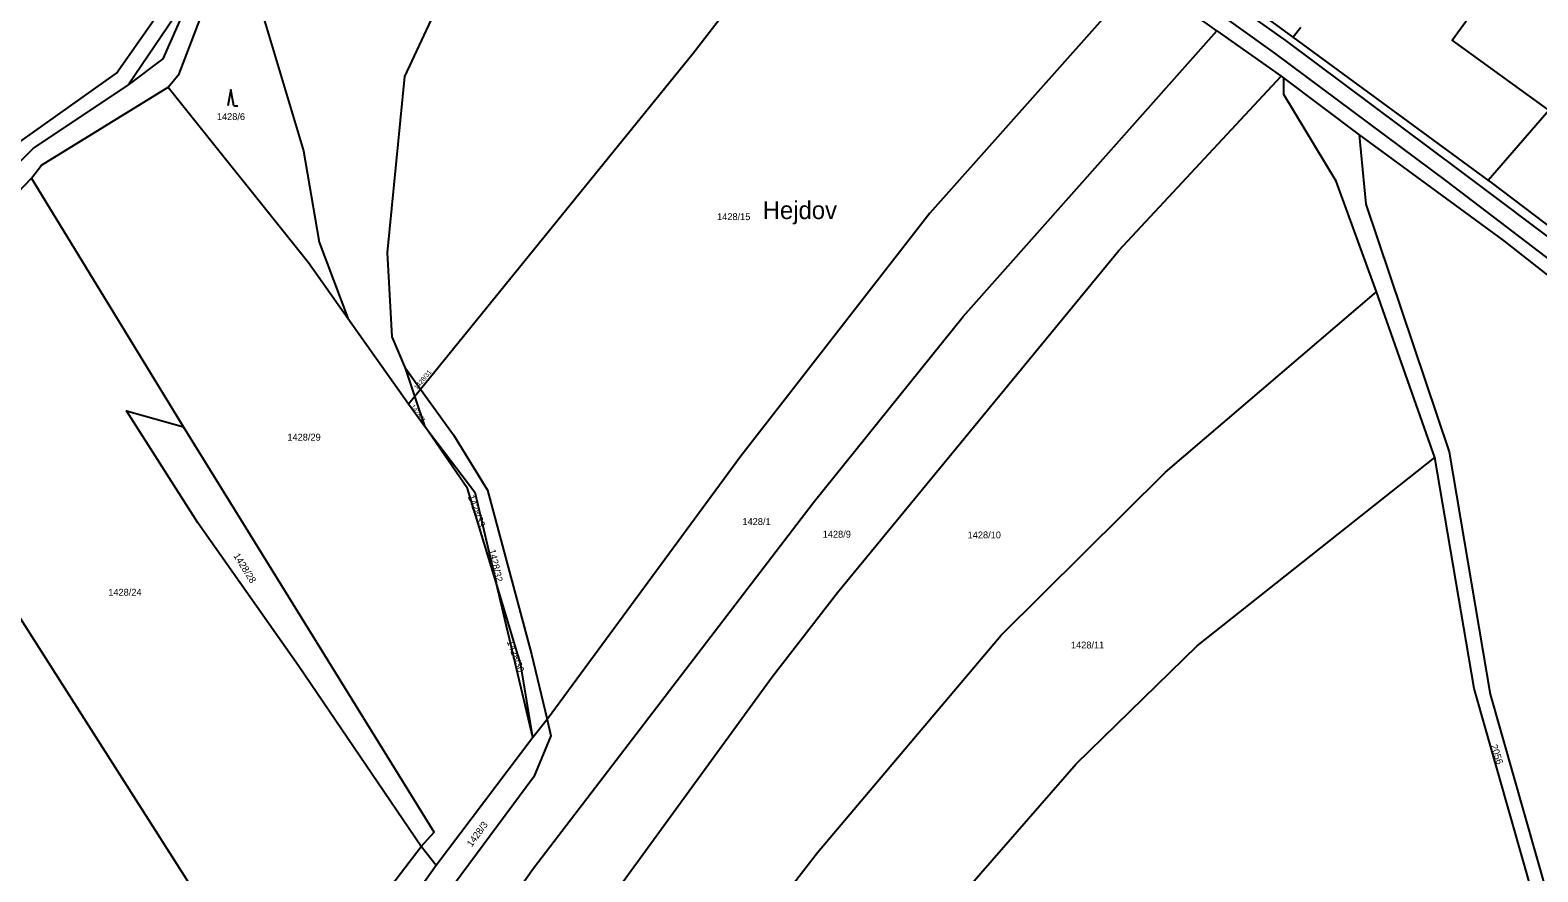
# Model space of a CAD drawing. Extents: x -679220 to -673243, y -1075091 to -1066557.
# Drawn here: x -677968.8 to -677596.9, y -1070610.2 to -1070402.6 of the extents above; entities that cross this region are included whole.
import ezdxf

# ---------------------------------------------------------------- set-up
doc = ezdxf.new("R2010")
doc.units = 0
for name, color, linetype in [('Hranice parcel', 7, 'Continuous'), ('Parcelní čísla', 7, 'Continuous'), ('Pop  PČ popisy', 7, 'Continuous'), ('Vnitřní kresba', 7, 'Continuous'), ('Značky kultur', 7, 'Continuous')]:
    doc.layers.add(name, color=color, linetype=linetype)

msp = doc.modelspace()

# ---------------------------------------------------------------- linework, layer by layer
at = {"layer": 'Hranice parcel'}
for p, q in [((-677676.01, -1070402.73), (-677694.91, -1070389.28)), ((-677676.01, -1070402.73), (-677660.17, -1070413.98)), ((-677655.29, -1070401.92), (-677657.23, -1070404.36)), ((-677609.13, -1070439.59), (-677657.23, -1070404.36)), ((-677660.17, -1070413.98), (-677659.51, -1070414.42)), ((-677659.51, -1070414.42), (-677640.92, -1070428.43)), ((-677930.97, -1070500.49), (-677968.48, -1070439.15)), ((-677622.29, -1070507.99), (-677636.62, -1070467.14)), ((-677890.42, -1070473.63), (-677875.44, -1070494.74)), ((-677873.92, -1070492.86), (-677876.21, -1070485.99)), ((-677876.21, -1070485.99), (-677872.51, -1070491.13)), ((-677875.44, -1070494.74), (-677873.92, -1070492.86)), ((-677873.92, -1070492.86), (-677872.51, -1070491.13)), ((-677871.38, -1070500.47), (-677873.92, -1070492.86)), ((-677875.44, -1070494.74), (-677871.38, -1070500.47)), ((-677844.81, -1070577.09), (-677853.87, -1070538.81)), ((-677841.24, -1070572.65), (-677844.81, -1070577.09)), ((-677844.81, -1070577.09), (-677868.63, -1070608.64)), ((-677906.8, -1070648.9), (-677872.33, -1070603.97)), ((-677868.63, -1070608.64), (-677872.33, -1070603.97)), ((-677868.63, -1070608.64), (-677896.62, -1070647.74))]:
    msp.add_line(p, q, dxfattribs=at)
for points in [[(-677594.18, -1070422.35), (-677617.99, -1070405.1), (-677595.86, -1070374.56), (-677562.79, -1070334.89), (-677527.98, -1070275.97), (-677483.78, -1070192.17), (-677443.31, -1070109.44)], [(-678202.72, -1070559.59), (-678196.24, -1070560.72), (-678173.74, -1070562.48), (-678126.52, -1070533.09), (-678089.52, -1070509.78), (-678070.97, -1070501.74), (-678009.17, -1070456.93), (-677947.5, -1070413.22), (-677923.47, -1070378.9), (-677909.43, -1070354.95), (-677894.19, -1070322.1), (-677883.78, -1070282.87), (-677858.64, -1070275.93)], [(-677855.84, -1070280.12), (-677880.02, -1070286.32), (-677890.13, -1070322.37), (-677903.96, -1070353.51), (-677931.48, -1070396.8), (-677944.62, -1070416.2)], [(-677944.62, -1070416.2), (-677936.01, -1070409.66), (-677930.66, -1070397.57), (-677918.45, -1070383.68), (-677909.53, -1070370.43), (-677886.19, -1070349.6), (-677870.36, -1070340.73), (-677870.09, -1070332.9), (-677876.85, -1070320.41), (-677873.44, -1070296.89), (-677853.32, -1070283.11)], [(-677876.21, -1070485.99), (-677879.53, -1070478.23), (-677880.65, -1070457.46), (-677876.4, -1070414), (-677860.23, -1070379.46), (-677858.39, -1070339.32), (-677865.38, -1070320.02), (-677859.97, -1070301.48), (-677838.54, -1070289.74)], [(-677872.51, -1070491.13), (-677805.2, -1070408.28), (-677756.66, -1070345.34)], [(-677657.23, -1070404.36), (-677700.73, -1070372.5), (-677730.02, -1070352.35)], [(-677934.76, -1070416.68), (-677932.07, -1070413.36), (-677926.94, -1070400.09), (-677915.46, -1070385.44)], [(-677915.46, -1070385.44), (-677901.39, -1070432.37), (-677897.5, -1070454.86), (-677890.42, -1070473.63)], [(-677694.91, -1070389.28), (-677746.88, -1070447.72), (-677793.45, -1070507.65), (-677841.24, -1070572.65)], [(-677874.94, -1070651.97), (-677873.69, -1070650.21), (-677844.6, -1070609.28), (-677775.61, -1070519.23), (-677738.63, -1070473.21), (-677676.01, -1070402.73)], [(-678001.62, -1070455.63), (-677993, -1070448.92), (-677976.44, -1070440.07), (-677967.96, -1070431.69), (-677944.62, -1070416.2)], [(-677854.13, -1070656.04), (-677853.11, -1070654.64), (-677785.75, -1070562.15), (-677769.67, -1070541.32), (-677700.26, -1070456.95), (-677660.17, -1070413.98)], [(-677636.62, -1070467.14), (-677646.59, -1070439.83), (-677659.5, -1070418.44), (-677659.51, -1070414.42)], [(-677968.48, -1070439.15), (-677966, -1070435.9), (-677934.76, -1070416.68)], [(-677934.76, -1070416.68), (-677900.16, -1070459.91), (-677890.42, -1070473.63)], [(-677609.13, -1070439.59), (-677605.88, -1070435.88), (-677594.18, -1070422.35)], [(-677640.92, -1070428.43), (-677605.25, -1070454.6), (-677571.87, -1070480.78), (-677536.71, -1070509.44), (-677502.3, -1070535.39), (-677460.61, -1070565.82), (-677445.99, -1070576.58)], [(-677640.92, -1070428.43), (-677639.26, -1070445.52), (-677618.77, -1070506.63), (-677608.64, -1070566.36), (-677585.89, -1070646.19), (-677563.48, -1070707.12)], [(-678017.52, -1070475.09), (-677994.05, -1070456.47), (-677974.84, -1070445.79), (-677968.48, -1070439.15)], [(-677539.06, -1070492.67), (-677608.27, -1070440.22), (-677609.13, -1070439.59)], [(-677819.01, -1070662.9), (-677818.21, -1070661.87), (-677774.56, -1070605.43), (-677729.28, -1070551.88), (-677688.72, -1070511.66), (-677636.62, -1070467.14)], [(-678017.52, -1070475.09), (-677962.07, -1070562.1), (-677906.8, -1070648.9)], [(-677872.51, -1070491.13), (-677864.36, -1070502.46), (-677855.97, -1070516.11), (-677845.11, -1070556.51), (-677841.24, -1070572.65)], [(-677872.33, -1070603.97), (-677902.64, -1070559.4), (-677927.45, -1070524.14), (-677945.06, -1070496.49), (-677930.97, -1070500.49)], [(-677872.33, -1070603.97), (-677869.15, -1070600.45), (-677930.97, -1070500.49)], [(-677853.87, -1070538.81), (-677860.88, -1070515.66), (-677871.38, -1070500.47)], [(-677871.38, -1070500.47), (-677859.14, -1070516.55), (-677853.87, -1070538.81)], [(-677780.46, -1070670.51), (-677779.92, -1070669.79), (-677743.21, -1070620.83), (-677710.76, -1070583.6), (-677680.88, -1070554.44), (-677622.29, -1070507.99)], [(-677566.31, -1070707.97), (-677586.34, -1070657.16), (-677612.59, -1070564.99), (-677622.29, -1070507.99)], [(-677844.81, -1070577.09), (-677847.71, -1070559.16), (-677853.87, -1070538.81)], [(-677841.24, -1070572.65), (-677840.32, -1070576.64), (-677844.55, -1070586.76), (-677889.11, -1070646.89), (-677896.62, -1070647.74)]]:
    msp.add_lwpolyline(points, dxfattribs=at)
at = {"layer": 'Vnitřní kresba'}
for p, q in [((-677659.05, -1070405.13), (-677734.73, -1070351.38)), ((-677661.76, -1070408.27), (-677736.82, -1070354.41)), ((-677616.07, -1070437.24), (-677659.05, -1070405.13)), ((-677619.21, -1070439.91), (-677661.76, -1070408.27)), ((-677546.87, -1070489.19), (-677616.07, -1070437.24)), ((-677549.4, -1070493.22), (-677619.21, -1070439.91))]:
    msp.add_line(p, q, dxfattribs=at)
at = {"layer": 'Značky kultur'}
for p, q in [((-677919.32, -1070417.23), (-677920.07, -1070421.23)), ((-677918.57, -1070421.23), (-677919.32, -1070417.23)), ((-677918.57, -1070421.23), (-677917.57, -1070421.23))]:
    msp.add_line(p, q, dxfattribs=at)

# ---------------------------------------------------------------- texts
at = {"layer": 'Parcelní čísla'}
for s, p in [('1428/6', (-677922.74, -1070424.78)), ('1428/15', (-677799.34, -1070449.46)), ('1428/29', (-677905.34, -1070503.85)), ('1428/1', (-677793.08, -1070524.67)), ('1428/9', (-677773.28, -1070527.79)), ('1428/10', (-677737.53, -1070527.97)), ('1428/24', (-677949.53, -1070542.11)), ('1428/11', (-677712.04, -1070555.12))]:
    msp.add_text(s, height=1.7, dxfattribs=at).set_placement(p)
for s, height, rotation, p in [('1428/31', 1.14, 50, (-677873.35, -1070491.36)), ('1428/7', 1.14, 305, (-677875, -1070495.42)), ('1428/33', 1.7, 290, (-677860.88, -1070517.63)), ('1428/28', 1.7, 302, (-677918.72, -1070532.26)), ('1428/32', 1.7, 283, (-677855.67, -1070530.84)), ('1428/30', 1.7, 290, (-677851.24, -1070553.43)), ('2056', 1.7, 288, (-677608.53, -1070579.09)), ('1428/3', 1.7, 54, (-677859.86, -1070604.21))]:
    msp.add_text(s, height=height, rotation=rotation, dxfattribs=at).set_placement(p)
at = {"layer": 'Pop  PČ popisy'}
msp.add_text('Hejdov', height=4.4, dxfattribs=at).set_placement((-677788.07, -1070449.2))

doc.saveas('drawing.dxf')
